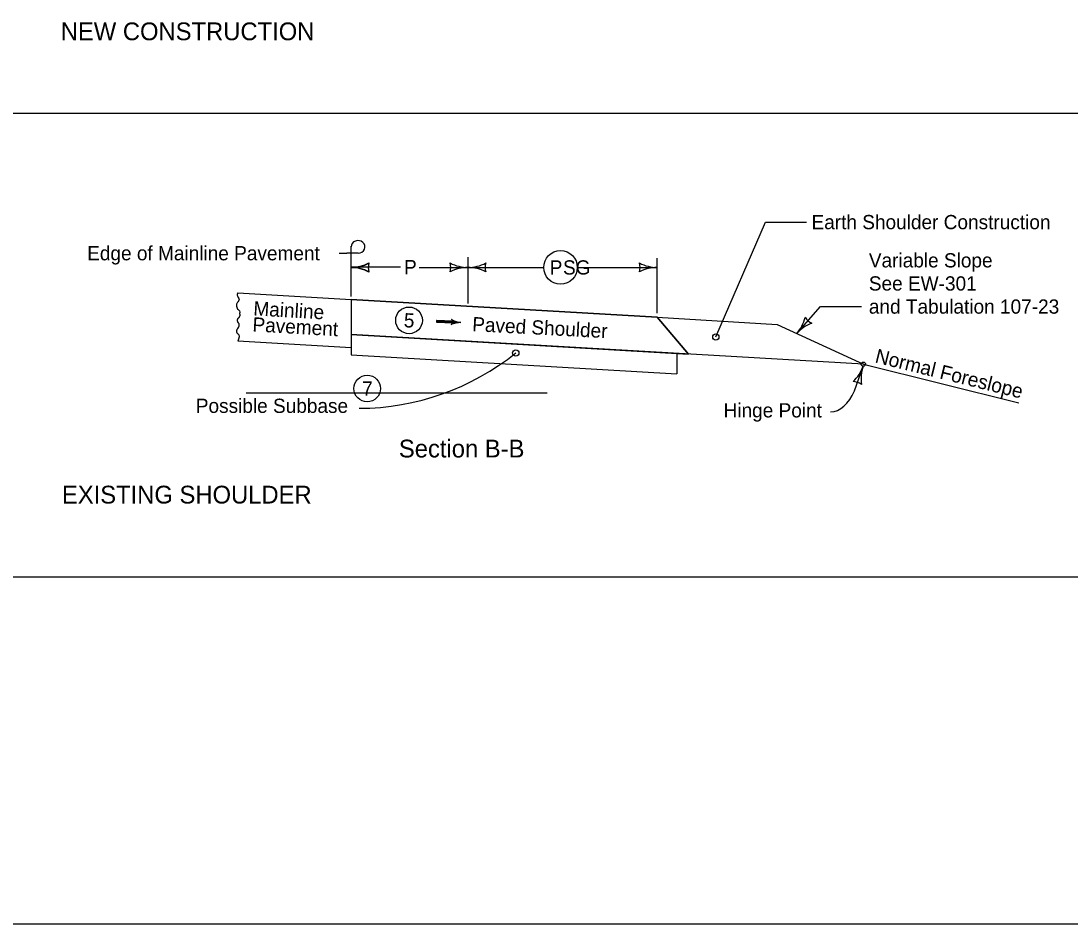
# Model space of a CAD drawing. Extents: x 10133 to 81668, y 7924 to 12229.
# Drawn here: x 11037 to 12217, y 7924 to 8940 of the extents above; entities that cross this region are included whole.
import ezdxf

# ---------------------------------------------------------------- set-up
doc = ezdxf.new("R2010")
doc.units = 0
for name, color, linetype in [('dsnTextFinalPlan', 7, 'Continuous'), ('Level 1', 7, 'Continuous'), ('Level 12', 7, 'Continuous'), ('Level 4', 7, 'Continuous'), ('Level 5', 7, 'Continuous'), ('Level 6', 7, 'Continuous'), ('SheetBorder', 7, 'Continuous')]:
    doc.layers.add(name, color=color, linetype=linetype)

msp = doc.modelspace()

# ---------------------------------------------------------------- linework, layer by layer
at = {"layer": 'dsnTextFinalPlan'}
for p, q in [((11281.2, 8633.9), (11408.7, 8626.4)), ((11408.7, 8626.4), (11408.7, 8572.4)), ((11408.7, 8626.4), (11753, 8606.4)), ((11753, 8606.4), (11408.7, 8626.4)), ((11408.7, 8626.4), (11408.7, 8586.9)), ((11752.5, 8606.6), (11752.5, 8606.6)), ((11753, 8606.5), (11887.7, 8598.1)), ((11753, 8606.4), (11788, 8565)), ((11788, 8565), (11753, 8606.4)), ((11887.7, 8598.1), (11984.8, 8553.6)), ((11281.2, 8579.8), (11408.7, 8572.4)), ((11984.8, 8553.6), (11408.7, 8586.9)), ((11408.7, 8586.9), (11788, 8565)), ((11775.2, 8580.1), (11775.2, 8580.1)), ((11408.7, 8572.4), (11408.7, 8564)), ((11408.7, 8564), (11775.2, 8542.9)), ((11775.2, 8565.7), (11775.2, 8542.9)), ((11984.8, 8553.6), (12159.8, 8510.3)), ((11290.6, 8521.5), (11629.1, 8521.5))]:
    msp.add_line(p, q, dxfattribs=at)
msp.add_circle((11473.8, 8602.9), 15, dxfattribs=at)
msp.add_ellipse((11984.8, 8553.6), major_axis=(2.58, 0), ratio=0.913811, dxfattribs=at)
for points in [[(11281.2, 8633.9), (11280.7, 8630.3), (11281.8, 8628.7), (11282.6, 8626.5), (11282, 8624.4), (11280.1, 8622), (11279.6, 8620.1), (11280.1, 8617.8), (11281, 8615.4), (11282, 8614.7), (11283.4, 8612.2), (11283.4, 8611.4)], [(11281.4, 8594.2), (11281.6, 8594.5), (11281.8, 8594.8), (11282.2, 8595.3), (11282.5, 8595.9), (11282.6, 8596.2), (11282.7, 8596.5), (11282.8, 8597.1), (11282.9, 8597.8), (11282.8, 8598.4), (11282.8, 8598.6), (11282.7, 8598.8), (11282.7, 8598.9), (11282.5, 8599.3), (11282.2, 8599.6), (11281.9, 8600), (11281.6, 8600.4), (11281.5, 8600.7), (11281.4, 8601), (11281.1, 8601.5), (11280.9, 8602.1), (11280.8, 8602.4), (11280.8, 8602.7), (11280.8, 8602.8), (11280.8, 8603), (11280.9, 8603.7), (11281.1, 8604.2), (11281.4, 8604.8), (11281.8, 8605.4), (11282.3, 8605.9), (11282.9, 8606.5), (11283.1, 8606.8), (11283.3, 8607.1), (11283.5, 8607.6), (11283.6, 8608.1), (11283.8, 8608.6), (11283.8, 8608.8), (11283.8, 8608.9), (11283.8, 8609), (11283.8, 8609.5), (11283.6, 8610.1), (11283.6, 8610.2), (11283.5, 8610.3), (11283.5, 8610.4), (11283.4, 8610.6), (11283.4, 8611.4)], [(11281.4, 8594.2), (11281.2, 8594), (11281, 8593.8), (11280.7, 8593.5), (11280.5, 8593.3), (11280.4, 8593), (11280.3, 8592.7), (11280, 8592.1), (11279.9, 8591.8), (11279.8, 8591.6), (11279.7, 8591.3), (11279.7, 8591.1), (11279.7, 8591), (11279.7, 8590.5), (11279.8, 8589.9), (11280, 8589.4), (11280.3, 8588.9), (11280.7, 8588.3), (11281.3, 8587.7), (11281.8, 8587.2), (11282, 8586.9), (11282.2, 8586.5), (11282.6, 8585.6), (11282.7, 8585.1), (11282.7, 8584.6), (11282.7, 8584.3), (11282.6, 8584.1), (11282.6, 8583.8), (11282.5, 8583.5), (11282.2, 8582.3), (11282, 8581.7), (11281.8, 8581.1), (11281.6, 8580.5), (11281.5, 8580.2), (11281.3, 8580), (11281.2, 8579.8)]]:
    msp.add_spline(points, degree=3, dxfattribs=at)
at = {"layer": 'Level 1'}
msp.add_line((10152.2, 8314.4), (13247.9, 8314.4), dxfattribs=at)
at = {"layer": 'Level 12'}
for centre in [(11473.8, 8602.9), (11426.8, 8526.2)]:
    msp.add_circle(centre, 15, dxfattribs=at)
at = {"layer": 'Level 4'}
msp.add_line((12307.8, 8835.4), (10152.2, 8835.4), dxfattribs=at)
for centre in [(11818.9, 8584.2), (11593.9, 8566.2)]:
    msp.add_circle(centre, 3.54, dxfattribs=at)
at = {"layer": 'Level 5'}
for p, q in [((11540.1, 8674), (11540.1, 8621.9)), ((11753, 8611.1), (11753, 8672.8)), ((11464.2, 8662.6), (11408.7, 8662.6)), ((11485.3, 8662.4), (11540.1, 8662.4)), ((11540.1, 8662.4), (11625.2, 8662.4)), ((11663.1, 8662.4), (11753, 8662.4))]:
    msp.add_line(p, q, dxfattribs=at)
msp.add_circle((11644.2, 8662.4), 18.9, dxfattribs=at)
for centre, radius, start, end in [((11408.7, 8705.1), 42.5, 270, 298.0725), ((11408.7, 8704.7), 42.5, 270, 298.0725), ((11408.7, 8620.1), 42.5, 61.9275, 90), ((11408.7, 8619.7), 42.5, 61.9275, 90), ((11444.3, 8662.6), 16.4, 162.2666, 197.7334), ((11444.3, 8662.2), 16.4, 162.2666, 197.7334), ((11504.4, 8662.4), 16.4, 342.2667, 17.7334), ((11540.1, 8704.9), 42.5, 241.9275, 270), ((11540.1, 8619.9), 42.5, 90, 118.0725), ((11540.1, 8704.9), 42.5, 270, 298.0725), ((11540.1, 8704.9), 42.5, 270, 298.0725), ((11540.1, 8619.9), 42.5, 61.9275, 90), ((11540.1, 8619.9), 42.5, 61.9275, 90), ((11575.7, 8662.4), 16.4, 162.2666, 197.7334), ((11575.7, 8662.4), 16.4, 162.2666, 197.7334), ((11717.3, 8662.4), 16.4, 342.2666, 17.7333), ((11753, 8704.9), 42.5, 241.9275, 270), ((11753, 8619.9), 42.5, 90, 118.0725), ((11417.2, 8786), 282, 270.132, 308.7946)]:
    msp.add_arc(centre, radius, start, end, dxfattribs=at)
at = {"layer": 'Level 6'}
for p, q in [((11818.9, 8584.2), (11874.6, 8713.4)), ((11874.6, 8713.4), (11921, 8713.4)), ((11408.7, 8665.5), (11408.7, 8686.4)), ((11395.3, 8678.4), (11404, 8678.4)), ((11416.5, 8678.4), (11404, 8678.4)), ((11408.7, 8629.6), (11408.7, 8665.5)), ((11909.9, 8588), (11936.5, 8618.4)), ((11936.5, 8618.4), (11982.9, 8618.4)), ((11523, 8600.9), (11504.8, 8602)), ((11523, 8601.9), (11523, 8601.9)), ((11522.9, 8600), (11522.9, 8600)), ((11975, 8523.7), (11984.5, 8551.3))]:
    msp.add_line(p, q, dxfattribs=at)
for points in [[(11523, 8601.9), (11504.8, 8602.9), (11504.7, 8601), (11522.9, 8600), (11522.9, 8601.6), (11505, 8602.7), (11505, 8601.2), (11522.5, 8600.3), (11522.6, 8601.4), (11505.3, 8602.4), (11505.2, 8601.4), (11522.3, 8600.5), (11522.4, 8601.2), (11505.5, 8602.2), (11505.4, 8601.7), (11522, 8600.7)], [(11522.6, 8603.1), (11523.3, 8602), (11523.3, 8600.3), (11522.5, 8598.9), (11525.2, 8599.8), (11528.4, 8600.4), (11529.3, 8600.6), (11527.1, 8601.1), (11523.9, 8602.4), (11522.9, 8602.9), (11523.1, 8599.4), (11528, 8600.6), (11523.4, 8602.2), (11523.4, 8599.8), (11526.8, 8600.7), (11523.8, 8601.5), (11523.5, 8600.2), (11525.7, 8600.7), (11524.1, 8601.2), (11524, 8600.5), (11524.8, 8600.7)]]:
    msp.add_lwpolyline(points, dxfattribs=at)
for centre, radius, start, end in [((11877.9, 8615.9), 42.5, 318.8454, 346.9178), ((11933.4, 8614.8), 16.4, 211.112, 246.5787), ((11941.9, 8560), 42.5, 110.7729, 138.8454), ((11944.3, 8565.1), 42.5, 312.9788, 341.0513), ((12024.7, 8537.5), 42.5, 161.0513, 189.1238), ((11972.9, 8517.6), 16.4, 53.3179, 88.7846)]:
    msp.add_arc(centre, radius, start, end, dxfattribs=at)
for centre, major_axis, ratio, start_param, end_param in [((11416.5, 8685.5), (-7.81, 0), 0.913811, 1.570796, 6.283185), ((11519.2, 8601.2), (3.88, 0), 0.913811, 5.202895, 7.237436), ((11534.2, 8620.6), (-22.2, 0), 0.913811, 0.954258, 1.478381), ((11531.5, 8580.2), (22.2, 0), 0.913811, 1.537172, 2.061295), ((11947.9, 8561.6), (0, 61.5), 0.559383, 3.141593, 4.048985)]:
    msp.add_ellipse(centre, major_axis=major_axis, ratio=ratio, start_param=start_param, end_param=end_param, dxfattribs=at)
at = {"layer": 'SheetBorder'}
msp.add_lwpolyline([(10132.5, 9944), (13267.5, 9944), (13267.5, 7924), (10132.5, 7924)], close=True, dxfattribs=at)

# ---------------------------------------------------------------- texts
at = {"layer": 'Level 12'}
msp.add_text('5', height=16, rotation=356.6997, dxfattribs=at).set_placement((11467.6, 8595.2))
msp.add_text('7', height=16, dxfattribs=at).set_placement((11421.1, 8518.2))
at = {"layer": 'Level 5'}
for s, p in [('P', (11468.2, 8654.8)), ('P', (11632, 8654.4)), ('SG', (11647, 8654.4))]:
    msp.add_text(s, height=16, dxfattribs=at).set_placement(p)
at = {"layer": 'Level 6'}
for s, height, p in [('NEW CONSTRUCTION', 20, (11082.1, 8917.9)), ('Earth Shoulder Construction', 16, (11926.5, 8705.4)), ('Edge of Mainline Pavement', 16, (11111.8, 8670.4)), ('Variable Slope', 16, (11991, 8662.4)), ('See EW-301', 16, (11991, 8636.4)), ('and Tabulation 107-23', 16, (11991, 8610.4)), ('Possible Subbase', 16, (11234, 8498.8)), ('Hinge Point', 16, (11827.6, 8493.7)), ('Section B-B', 20, (11462.4, 8448.7)), ('EXISTING SHOULDER', 20, (11083.4, 8396.9))]:
    msp.add_text(s, height=height, dxfattribs=at).set_placement(p)
for s, rotation, p in [('Mainline', 356.7346, (11298.4, 8608.5)), ('Pavement', 356.7346, (11297.4, 8590.5)), ('Paved Shoulder ', 356.983, (11544.6, 8590.8)), ('Normal Foreslope', 346.0988, (11997, 8555.7))]:
    msp.add_text(s, height=16, rotation=rotation, dxfattribs=at).set_placement(p)

doc.saveas('drawing.dxf')
